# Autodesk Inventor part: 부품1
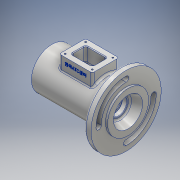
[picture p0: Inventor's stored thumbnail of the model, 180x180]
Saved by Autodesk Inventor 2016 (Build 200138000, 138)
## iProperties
Created: 2017-05
Part Number: 부품1
Material: 알루미늄 6061
Document SubType Name: Modeling
Designer: USER
Mass: 678.719 g
Surface Area: 617.984 cm^2
Volume: 251.378 cm^3
Density: 2.7 g/cm^3
Appearance: 알루미늄 - 평지
Author: USER
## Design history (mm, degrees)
sketch "스케치1"
  geometry: L1 (0, 0)-(0, 31); L2 (0, 31)-(102, 31); L3 (102, 31)-(102, 50); L4 (105, 53)-(112, 53); L5 (112, 53)-(112, 31); L6 (112, 31)-(115, 31); L7 (115, 31)-(115, 0); L8 (115, 0)-(0, 0); L9 (9, 0)-(9, 24); L10 (9, 24)-(12, 24); L11 (12, 24)-(12, 20); L12 (21, 20)-(21, 17.5); L13 (21, 17.5)-(24.25, 17.5); L14 (24.25, 17.5)-(24.25, 18.5); L15 (24.25, 18.5)-(26, 18.5); L16 (26, 18.5)-(26, 17.5); L17 (26, 17.5)-(36, 17.5); L18 (37, 18.5)-(37, 23); L19 (40, 26)-(72, 26); L20 (75, 23)-(75, 18.5); L21 (76, 17.5)-(85.7, 17.5); L22 (86, 17.2)-(86, 16.5); L23 (12, 20)-(21, 20); L24 (86, 16.5)-(88, 16.5); L25 (91, 13.5)-(91, 10); L26 (91, 10)-(93.7, 10); L27 (93.7, 10)-(93.7, 12.2); L28 (94, 12.5)-(100.3, 12.5); L29 (100.3, 12.5)-(101, 12.904); L30 (101, 12.904)-(101, 14.455); L31 (102.903, 17.248)-(115, 22); L32 (36, 17.5)-(37, 18.5); L33 (76, 17.5)-(75, 18.5); A1 r 3 centre (104, 14.455) between (102.903, 17.248) and (101, 14.455); A2 r 0.3 centre (94, 12.2) between (94, 12.5) and (93.7, 12.2); A3 r 3 centre (88, 13.5) between (91, 13.5) and (88, 16.5); A4 r 3 centre (40, 23) between (40, 26) and (37, 23); A5 r 3 centre (72, 23) between (75, 23) and (72, 26); A6 r 3 centre (105, 50) between (105, 53) and (102, 50); A7 r 0.3 centre (85.7, 17.2) between (86, 17.2) and (85.7, 17.5); 5 further points
  constraints: 66 end point, 18 perpendicular, 14 point on circle, 14 point on line, 14 tangent, 7 centre point, 5 vertical, 3 equal radius, 3 horizontal
  dimensions: "d0" = 115 distance between parallel lines of L7 L1; "d1" = 3 distance between parallel lines of L7 L5; "d2" = 13 distance between parallel lines of L7 L3; "d3" = 106 diameter of L4 L8; "d4" = 62 diameter of L6 L8; "d5" = 62 diameter of L2 L8; "d7" = 48 diameter of L10 L8; "d10" = 3 distance between parallel lines of L11 L9; "d11" = 12 distance from line of L11.end L1; "d12" = 40 diameter of L23 L8; "d13" = 21 distance between parallel lines of L1 L12; "d14" = 35 diameter of L13 L8; "d15" = 37 diameter of L15 L8; "d16" = 1.75 distance between parallel lines of L16 L14; "d17" = 26 distance between parallel lines of L16 L1; "d18" = 35 diameter of L17 L8; "d19" = 52 diameter of L19 L8; "d20" = 11 distance between parallel lines of L18 L16; "d21" = 11 distance between parallel lines of L22 L20; "d22" = 35 diameter of L21 L8 (derived); "d24" = 38 distance between parallel lines of L20 L18; "d27" = 33 diameter of L24 L8; "d29" = 20 diameter of L26 L8; "d30" = 25 diameter of L28 L8; "d31" = 5 distance of L22.end point (91, 16.5); "d32" = 2.7 distance of L25.end L26.end; "d34" = 0.7 distance from line of L30 L28.end; "d35" = 30 deg angle of L29 L28; "d36" = 44 diameter of L31.end L8; "d37" = 33 diameter of point (101, 16.5) L8; "d38" = 14 distance between parallel lines of L7 L30; "d39" = 3 radius of A1; "d40" = 0.3 radius of A2; "d41" = 1 distance of L17.end point (37, 17.5); "d42" = 1 distance of L18.start point (37, 17.5) (= d41); "d43" = 1 distance of L21.start point (75, 17.5) (= d41); "d44" = 1 distance of L20.end point (75, 17.5) (= d43); "d45" = 3 radius of A6; "d98" = 7.3 distance between parallel lines of L30 L27 (derived); "d99" = 0.3 radius of A7
revolve "회전1" sketch "스케치1" stored, may be unused: angle "d46" = 90 deg
hole "구멍1" diameter "d49" = 40.376; stored, may be unused: countersink angle "d53" = 90 deg, drill point angle "d55" = 0 deg; dims "d47" = 10, "d48" = 10, "d50" = 12, "d51" = 4, "d52" = 2, "d54" = 12
chamfer "모따기1" distance "d56" = 1; stored, may be unused: second distance "d57" = 2, angle "d58" = 45 deg
sketch "스케치2"
  geometry: L1 (0, 37.5)-(0, 45.5); L2 (37.5, 0)-(45.5, 0); L3 (-37.5, 0)-(-45.5, 0); L4 (0, -45.5)-(0, -37.5); C1 r 41.5 at (0, 0); C2 r 53 at (0, 0) reference; A1 r 4 centre (0, 41.5) between (0, 45.5) and (0, 37.5); A2 r 4 centre (41.5, 0) between (37.5, 0) and (45.5, 0); A3 r 4 centre (-41.5, 0) between (-37.5, 0) and (-45.5, 0); A4 r 4 centre (0, -41.5) between (0, -45.5) and (0, -37.5); A5 r 37.5 centre (0, 0) between (-37.5, 0) and (0, -37.5); A6 r 37.5 centre (0, 0) between (37.5, 0) and (0, 37.5); A7 r 45.5 centre (0, 0) between (-45.5, 0) and (0, -45.5); A8 r 45.5 centre (0, 0) between (45.5, 0) and (0, 45.5); 5 further points
  constraints: 16 point on circle, 9 centre point, 8 end point, 7 coincident, 4 midpoint, 2 horizontal alignment, 2 perpendicular, 2 vertical alignment, 1 horizontal, 1 vertical
  dimensions: "d59" = 83 diameter of C1; "d62" = 45.5 radius of A7; "d63" = 37.5 radius of A5; "d64" = 37.5 radius of A6; "d65" = 45.5 radius of A8
extrude "돌출1" cut sketch "스케치2" distance "d66" = 30; taper "d67" = 0 deg
node "작업 평면1"
sketch "스케치3"
  geometry: L1 (31, -20)-(81, -20); L2 (81, -20)-(81, 20); L3 (81, 20)-(31, 20); L4 (31, 20)-(31, -20); 4 further points
  constraints: 8 end point, 2 horizontal alignment, 2 midpoint, 2 parallel, 1 horizontal, 1 perpendicular, 1 vertical alignment
  dimensions: "d69" = 56 distance of point (56, 0) point (0, 0); "d70" = 40 distance of L3.end L1.start; "d71" = 50 distance of L1.start L1.end
extrude "돌출2" join sketch "스케치3" stored distance "d72" = 30; taper "d73" = 0 deg
sketch "스케치4"
  geometry: L1 (40, 11)-(72, 11); L2 (72, 11)-(72, -11); L3 (72, -11)-(40, -11); L4 (40, -11)-(40, 11); L5 (81, 20)-(31, 20) reference; L6 (31, 20)-(31, -20) reference; 5 further points
  constraints: 8 end point, 4 midpoint, 2 parallel, 1 horizontal, 1 horizontal alignment, 1 perpendicular, 1 vertical alignment
  dimensions: "d74" = 32 distance of L2.end L3.end; "d75" = 22 distance of L3.end L1.start
extrude "돌출3" cut sketch "스케치4" distance "d76" = 46; taper "d77" = 0 deg
sketch "스케치5"
  geometry: L1 (35.5, 15.5)-(76.5, 15.5); L2 (76.5, 15.5)-(76.5, -15.5); L3 (76.5, -15.5)-(35.5, -15.5); L4 (35.5, -15.5)-(35.5, 15.5); L5 (40, 11)-(72, 11) reference; L6 (40, -11)-(40, 11) reference; 9 further points
  constraints: 8 end point, 4 coincident, 4 midpoint, 2 parallel, 1 horizontal, 1 horizontal alignment, 1 perpendicular, 1 vertical alignment
  dimensions: "d78" = 41 distance of L2.end L3.end; "d79" = 31 distance of L3.end L1.start
hole "구멍2" sketch "스케치5" at (35.5, 15.5), (35.5, -15.5), (76.5, 15.5), (76.5, -15.5) diameter "d80" = 2.459; stored, may be unused: countersink angle "d84" = 90 deg, drill point angle "d86" = 120 deg; dims "d81" = 6, "d82" = 4, "d83" = 2, "d85" = 8
fillet "모깎기1" dims "d87" = 3
chamfer "모따기2" distance "d88" = 1; stored, may be unused: second distance "d89" = 2, angle "d90" = 45 deg
fillet "모깎기2" dims "d91" = 3
fillet "모깎기3" dims "d92" = 3
node "작업 평면2"
sketch "스케치6"
  geometry: L1 (0, -31)-(0, 31) reference; L2 (34, 44)-(78, 44) reference; 2 further points
  constraints: 1 other
  dimensions: "d94" = 56 distance from line of point (56, 36) L1; "d95" = 8 distance from line of point (56, 36) L2
feature "엠보싱1" sketch "스케치6" dims "d96" = 0.5, "d97" = 0
node "솔리드1"
other parameters: "d60" = 91, "d61" = 75, "d68" = 44
